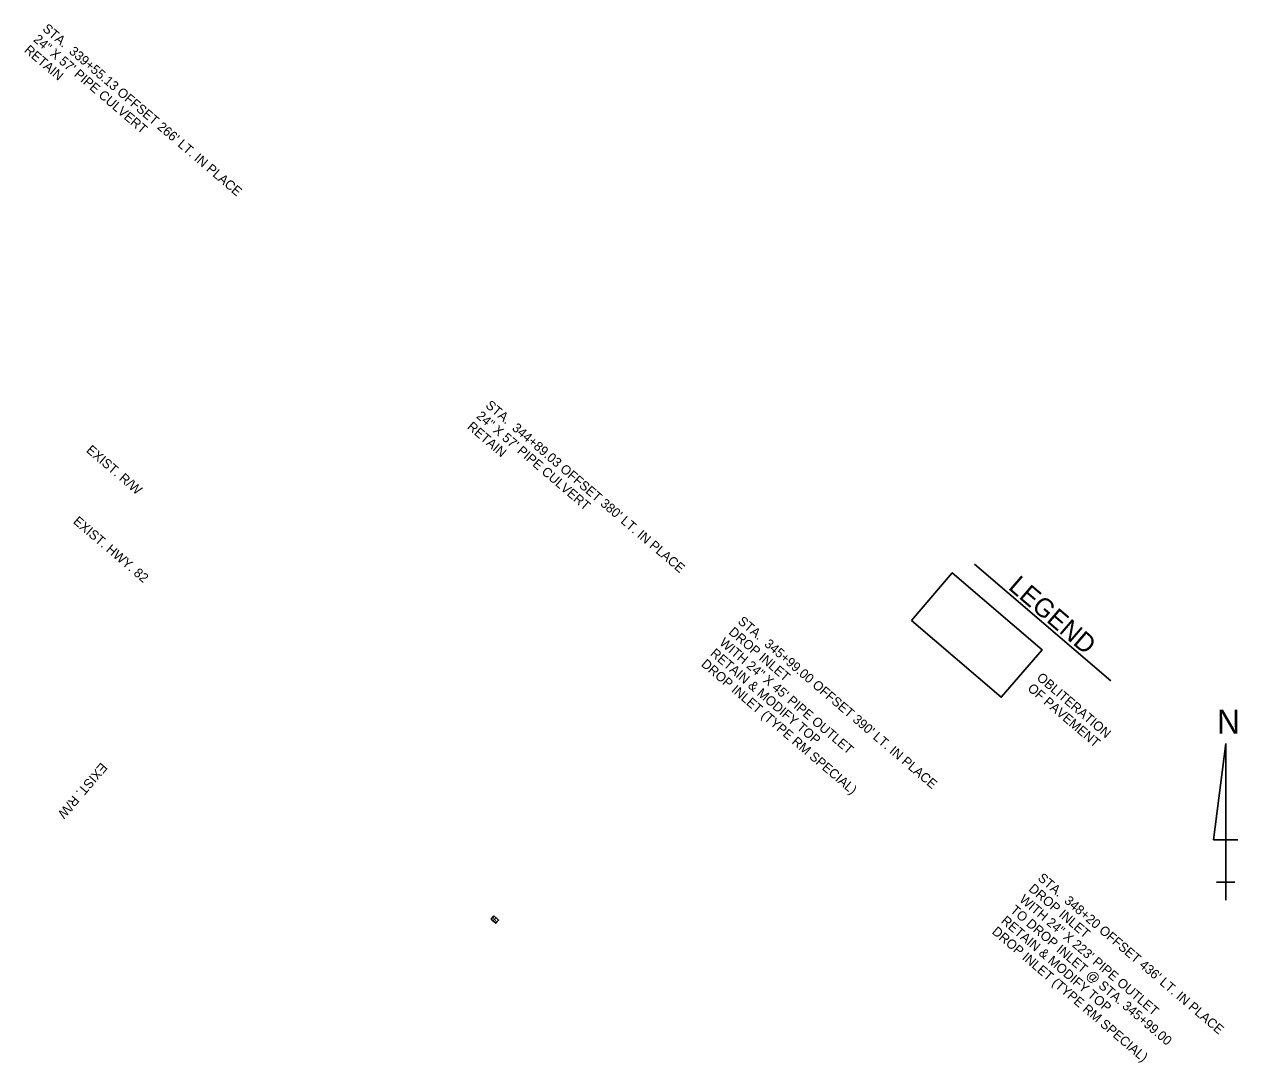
# Model space of a CAD drawing. Extents: x 884041 to 885169, y 1564878 to 1566399.
# Drawn here: x 884041 to 884816, y 1565735 to 1566399 of the extents above; entities that cross this region are included whole.
import ezdxf

# ---------------------------------------------------------------- set-up
doc = ezdxf.new("R2010")
doc.units = 0
for name, color, linetype in [('Default', 7, 'Continuous'), ('R_Border', 7, 'Continuous'), ('S_SECONDARY_CTL_ANNOT', 7, 'Continuous'), ('S_SURVEY_TEXT_ANNOT', 7, 'Continuous')]:
    doc.layers.add(name, color=color, linetype=linetype)

msp = doc.modelspace()

# ---------------------------------------------------------------- linework, layer by layer
at = {"layer": 'Default'}
for p, q in [((884808.71, 1565939.28), (884801.02, 1565877.74)), ((884808.71, 1565839.28), (884808.71, 1565939.28)), ((884808.71, 1565939.28), (884808.71, 1565862.35)), ((884801.02, 1565877.74), (884816.41, 1565877.74)), ((884808.71, 1565839.28), (884808.71, 1565862.35)), ((884808.71, 1565850.81), (884802.94, 1565850.81)), ((884802.94, 1565850.81), (884814.48, 1565850.81)), ((884808.71, 1565839.28), (884808.71, 1565850.81))]:
    msp.add_line(p, q, dxfattribs=at)
at = {"layer": 'R_Border'}
msp.add_line((884648.14, 1566054.01), (884735.32, 1565979.38), dxfattribs=at)
for points in [[(884607.95, 1566018.05), (884665.35, 1565968.91), (884691.36, 1565999.3), (884633.96, 1566048.44)], [(884341.08, 1565829.17), (884344.17, 1565826.52), (884342.45, 1565824.52), (884339.36, 1565827.17)]]:
    msp.add_lwpolyline(points, close=True, dxfattribs=at)
at = {"layer": 'S_SECONDARY_CTL_ANNOT'}
msp.add_lwpolyline([(884607.95, 1566018.05), (884665.35, 1565968.91), (884691.36, 1565999.3), (884633.96, 1566048.44), (884607.95, 1566018.05)], dxfattribs=at)

# ---------------------------------------------------------------- texts
at = {"layer": 'Default'}
msp.add_text('N', height=15.38, dxfattribs=at).set_placement((884803.08, 1565945.69))
at = {"layer": 'R_Border'}
for s, height, rotation, p in [("STA.  339+55.13 OFFSET 266' LT. IN PLACE", 6, 319.43354, (884052.26, 1566395.31)), ('24" X 57\' PIPE CULVERT', 6, 319.43354, (884046.41, 1566388.47)), ('RETAIN ', 6, 319.43354, (884040.56, 1566381.64)), ("STA.  344+89.03 OFFSET 380' LT. IN PLACE", 6, 319.43354, (884335.33, 1566154.66)), ('24" X 57\' PIPE CULVERT', 6, 319.43354, (884329.48, 1566147.83)), ('RETAIN ', 6, 319.43354, (884323.62, 1566140.99)), ('EXIST. R/W', 6, 319.43354, (884080.21, 1566126.04)), ('EXIST. HWY. 82', 6, 319.43354, (884071.85, 1566080.54)), ('LEGEND', 12, 319.43349, (884669.21, 1566038.44)), ("STA.  345+99.00 OFFSET 390' LT. IN PLACE", 6, 319.43349, (884496.52, 1566016.67)), ('WITH 24" X 45\' PIPE OUTLET', 6, 319.43349, (884484.81, 1566003)), ('DROP INLET ', 6, 319.43349, (884490.67, 1566009.83)), ('RETAIN & MODIFY TOP', 6, 319.43349, (884478.96, 1565996.16)), ('DROP INLET (TYPE RM SPECIAL)', 6, 319.43349, (884473.11, 1565989.32)), ('OF PAVEMENT', 6, 319.43349, (884681.66, 1565973.79)), ('OBLITERATION ', 6, 319.43349, (884687.51, 1565980.63)), ('EXIST. R/W', 6, 229.43354, (884090.16, 1565927.58)), ("STA.  348+20 OFFSET 436' LT. IN PLACE", 6, 319.43349, (884688.17, 1565852.6)), ('DROP INLET', 6, 319.43349, (884682.32, 1565845.76)), ('WITH 24" X 223\' PIPE OUTLET', 6, 319.43349, (884676.47, 1565838.92)), ('RETAIN & MODIFY TOP', 6, 319.43349, (884664.76, 1565825.25)), ('TO DROP INLET @ STA. 345+99.00', 6, 319.43349, (884670.61, 1565832.09)), ('DROP INLET (TYPE RM SPECIAL)', 6, 319.43349, (884658.91, 1565818.41))]:
    msp.add_text(s, height=height, rotation=rotation, dxfattribs=at).set_placement(p)
at = {"layer": 'S_SURVEY_TEXT_ANNOT'}
msp.add_text('+', height=6, rotation=217.47218, dxfattribs=at).set_placement((884341.65, 1565830.7))

doc.saveas('drawing.dxf')
